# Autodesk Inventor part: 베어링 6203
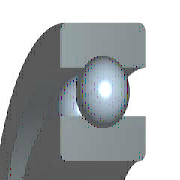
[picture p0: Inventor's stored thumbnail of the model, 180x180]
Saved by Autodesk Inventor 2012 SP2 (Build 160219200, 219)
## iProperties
IsCustomPart: 0
Company: 한국ATC센터
Created: 2014-10
Part Number: 베어링 6203
Material: Steel, Mild
Description: 깊은 그루브 볼 베어링
Document SubType Name: Modeling
Standard: KS B 2023
Designer: KYOUNG IL JANG
Standards Organization: KS
Language: ko-KR
Size Designation: 6203 - 17 x 40 x 12
Categories: <MemberInstance><Categories><Category DisplayName="샤프트 부품" InternalName="7f7aeb1f-a693-4053-b835-cee3144e0d98" Mnemonic="SHFT"><Category DisplayName="베어링" Inter
Density: 7.86 g/cm^3
Mass: 64.9809 g
Surface Area: 64.3582 cm^2
Volume: 8.26729 cm^3
Author: KYOUNG IL JANG
Revision Number: 1
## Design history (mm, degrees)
revolve "본체" stored, may be unused: angle "d6" = 90 deg
revolve "볼" stored, may be unused: angle "d7" = 90 deg
pattern_circular "IDS_ARRAYBALL[SIMPL:T]" dims angle "d3" = 360 deg
body "Solid1"
sketch "스케치" dims "d0" = 5.98 (= -0.26 x WD + 0.26 x BD)
  geometry: L1 (3.01, 14.25)-(8.99, 14.25); L2 (6, 14.25)-(6, 11.26); L3 (6, 14.25)-(6, 17.24); L4 (3.778, 12.249)-(0, 12.249); L5 (0, 8.5)-(12, 8.5); L6 (3.778, 16.251)-(0, 16.251); L7 (0, 20)-(12, 20); L8 (12, 8.5)-(12, 12.249); L9 (8.222, 12.249)-(12, 12.249); L10 (8.222, 16.251)-(12, 16.251); L11 (12, 20)-(12, 16.251); L12 (-1.4, 0)-(8.4, 0) reference; L13 (0, -0.3)-(0, 5.3) reference
  constraints: 22 end point, 4 point on line, 2 collinear, 2 perpendicular, 2 symmetric about line, 1 midpoint, 1 parallel, 14 other
  dimensions: "d9" = 17 diameter of L5 L12 (= WD); "d11" = 40 diameter of L7 L12 (= BD); "d12" = 12 distance between parallel lines of L8 L13 (= KB); "d13" = 24.498 diameter of L9 L12 (= 0.326 x BD + 0.674 x WD)
fillet "모깎기1" dims "d1" = 0.6 (= KRS)
other parameters: "WD" = 17 [user parameter; used in 5 equation terms], "BD" = 40 [user parameter; used in 5 equation terms], "KB" = 12 [user parameter; used in 1 equation term], "KRS" = 0.6 [user parameter; used in 1 equation term], "d4" = 0, "d5" = 0, "d8" = 0, "d14" = 0, "d15" = 0, "BBA" = 0 [user parameter], "BC0" = 4750000 [user parameter], "BC" = 9560000 [user parameter], "WR" = 8.5 (= 0.5 x WD) [user parameter]
